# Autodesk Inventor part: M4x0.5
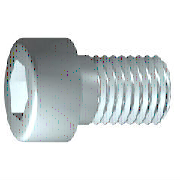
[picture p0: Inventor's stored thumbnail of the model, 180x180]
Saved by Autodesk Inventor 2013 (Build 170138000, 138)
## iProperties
IsCustomPart: 1
Company: 한국ATC센터
Created: 2014-10
Part Number: M4x0.5
Material: 강, 연강
Description: 6각머리 태핑 나사
Document SubType Name: Modeling
Standard: KS B 1003
Designer: 한국ATC센터
Standards Organization: KS
Language: ko-KR
Size Designation: M 4 x 16
Categories: <MemberInstance><Categories><Category DisplayName="조임쇠" InternalName="e4da775c-781d-43d5-af7c-5136215cf5a6" Mnemonic="FSTN"><Category DisplayName="볼트" InternalN
Density: 7.86 g/cm^3
Mass: 2.62973 g
Surface Area: 3.81119 cm^2
Volume: 0.334572 cm^3
Author: KYOUNG IL JANG
Revision Number: 1
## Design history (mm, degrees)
sketch "스케치1"
  geometry: L1 (-1, 0)-(16, 0); L2 (16, 0)-(16, 2); L3 (16, 2)-(1.75, 2); L4 (1.75, 2)-(1.32, 2); L5 (1.32, 2)-(0, 2); L6 (0, 2)-(0, 3.5); L7 (0, 3.5)-(-4, 3.5); L8 (-4, 3.5)-(-4, 1.732); L9 (-4, 1.732)-(-2, 1.732); L10 (-2, 1.732)-(-1, 0); L11 (-8, 0)-(20, 0) reference; L12 (0, -0.7)-(0, 4.2) reference; L13 (1.75, 2)-(0, 2)
  constraints: 22 end point, 6 parallel, 2 collinear, 2 perpendicular, 1 horizontal, 1 point on line
  dimensions: "d1" = 14.25 distance from line of L3.end L2 (= GEL); "d2" = 0.42952 distance of L4.end L3.end (computed from GAL); "d3" = 4 distance between parallel lines of L8 L6 (= KOH); "d4" = 2 distance of L8.end L9.end (= INTI); "d5" = 60 deg angle of L10 L1; "d6" = 4 diameter of L3 L1 (= GD); "d7" = 4 diameter of L5 L1 (= BDM); "d8" = 3.4641 diameter of L9 L1 (= 1.1547 x SW); "d9" = 7 diameter of L7 L1 (= KOD); "d26" = 16 distance between parallel lines of L12 L2 (= NLG)
revolve "본체" sketch "스케치1" stored, may be unused: angle "d10" = 90 deg
sketch "스케치2"
  geometry: L1 (0, -4.9)-(0, 4.9) reference; L2 (-4.9, 0)-(4.9, 0) reference; L3 (1.732, 0)-(0.866, -1.5); L4 (0.866, -1.5)-(-0.866, -1.5); L5 (-0.866, -1.5)-(-1.732, 0); L6 (-1.732, 0)-(-0.866, 1.5); L7 (-0.866, 1.5)-(0.866, 1.5); L8 (0.866, 1.5)-(1.732, 0); 2 further points
  constraints: 12 end point, 1 coincident, 1 horizontal alignment, 1 point on line, 12 other
extrude "슬롯" join sketch "스케치2" stored distance "d11" = 10; taper "d12" = 0 deg
workplane "Work Plane1"
fillet "Fillet2" dims "d30" = 0.1 (= R)
body "Solid1"
fillet "모깎기1" dims "d17" = 0.4 (= RR)
feature "스레드" dims "d13" = 14.25 (= GEL), "d14" = 0
chamfer "모따기1" distance "d15" = 0.42941 (= -0.5 x SPD + 0.5 x GD); stored, may be unused: second distance "d16" = 0.42941 (= GUL), angle "d27" = 45 deg
other parameters: "GD" = 4 (= NND) [user parameter; used in 2 equation terms], "NLG" = 16 [user parameter; used in 1 equation term], "GEL" = 14.25 [user parameter; used in 2 equation terms], "KOD" = 7 [user parameter; used in 1 equation term], "KOH" = 4 [user parameter; used in 1 equation term], "INTI" = 2 [user parameter; used in 1 equation term], "GAL" = 0.42941 (= 0.61345 x PTC) [user parameter; used in 1 equation term], "GUL" = 0.42941 (= 0.61345 x PTC) [user parameter; used in 1 equation term], "BDM" = 4 (= NND) [user parameter; used in 1 equation term], "SW" = 3 [user parameter; used in 2 equation terms], "RR" = 0.4 [user parameter; used in 1 equation term], "SPD" = 3.14117 (= NND - 1.2269 x PTC) [user parameter; used in 1 equation term], "d19" = 0, "d28" = 0, "d29" = 0, "R" = 0.1 [user parameter; used in 1 equation term], "PHH" = 0.2 [user parameter], "GD1" = 3.14117 (= THREADDIA - 1.2269 x PTC) [user parameter], "THREADDIA" = 4 [user parameter; used in 1 equation term], "FAWI" = 45 deg [user parameter], "TPU" = 14.28571 (computed from PTC) [user parameter], "PTC" = 0.7 [user parameter; used in 5 equation terms], "NND" = 4 [user parameter; used in 3 equation terms], "TOA" = 30 deg [user parameter], "E0" = 3.465 (= 1.155 x SW) [user parameter]
